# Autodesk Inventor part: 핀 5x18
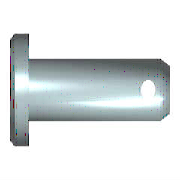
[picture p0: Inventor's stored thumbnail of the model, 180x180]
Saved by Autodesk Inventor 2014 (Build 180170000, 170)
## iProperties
Created: 2012-02
Part Number: 핀 5x18
Material: 강철
Description: 머리가 있는 클레비스 핀
Document SubType Name: Modeling
Standard: ISO 2341
Designer: test
Standard Revision: Second edition 1986-11-01
Standards Organization: ISO
Language: ko-KR
Size Designation: B - 5 x 18
Categories: <MemberInstance><Categories><Category DisplayName="조임쇠" InternalName="e4da775c-781d-43d5-af7c-5136215cf5a6" Mnemonic="FSTN"><Category DisplayName="핀" InternalNa
Density: 7.85 g/cm^3
Appearance: 강철
IsCustomPart: 1
Author: test
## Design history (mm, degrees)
sketch "스케치1"
  geometry: L1 (-1.6, 0)-(-1.6, 4); L2 (-1.6, 4)-(0, 4); L3 (0, 4)-(0, 2.5); L4 (0, 2.5)-(18, 2.5); L5 (18, 2.5)-(18, 0); L6 (-1.6, 0)-(18, 0); L7 (-4, 0)-(17, 0) reference; L8 (0, -0.98)-(0, 3.08) reference; C1 r 0.6 at (15.1, 0)
  constraints: 12 end point, 3 parallel, 2 collinear, 2 perpendicular, 1 centre point, 1 point on line, 1 vertical
  dimensions: "d0" = 5 diameter of L4 L6 (= NND); "d1" = 8 diameter of L2 L6 (= KOD); "d2" = 1.6 distance of L1.end L2.end (= KOH); "d3" = 18 distance of L3.end L4.end (= NLG); "d5" = 2.9 distance from line of L5 C1.centre (= DIST); "d6" = 1.2 diameter of C1 (= BOR)
revolve "본체" stored, may be unused: angle "d4" = 90 deg
extrude "구멍" cut sketch "스케치1" stored distance "d7" = 5 (= NND); taper "d8" = 0 deg
workaxis "Work Axis1"
workplane "Work Plane1"
body "Solid1"
chamfer "모따기1" distance "d9" = 1 (= PHH2); stored, may be unused: angle "d10" = 45 deg (= FAWI2), second distance "d16" = 1 (= PHH2)
chamfer "모따기2" distance "d11" = 2 (= PHH1); stored, may be unused: angle "d12" = 30 deg (= FAWI1), second distance "d17" = 2 (= PHH1)
other parameters: "PHH1" = 2 [user parameter; used in 2 equation terms], "PHH2" = 1 [user parameter; used in 2 equation terms], "KOD" = 8 [user parameter; used in 1 equation term], "KOH" = 1.6 [user parameter; used in 1 equation term], "NND" = 5 [user parameter; used in 2 equation terms], "FAWI1" = 30 deg [user parameter; used in 1 equation term], "FAWI2" = 45 deg [user parameter; used in 1 equation term], "DIST" = 2.9 [user parameter; used in 1 equation term], "BOR" = 1.2 [user parameter; used in 1 equation term], "NLG" = 18 [user parameter; used in 1 equation term], "d13" = 0, "d14" = 0, "d27" = 0, "d28" = 0, "d29" = 0, "d30" = 0, "d31" = 0
